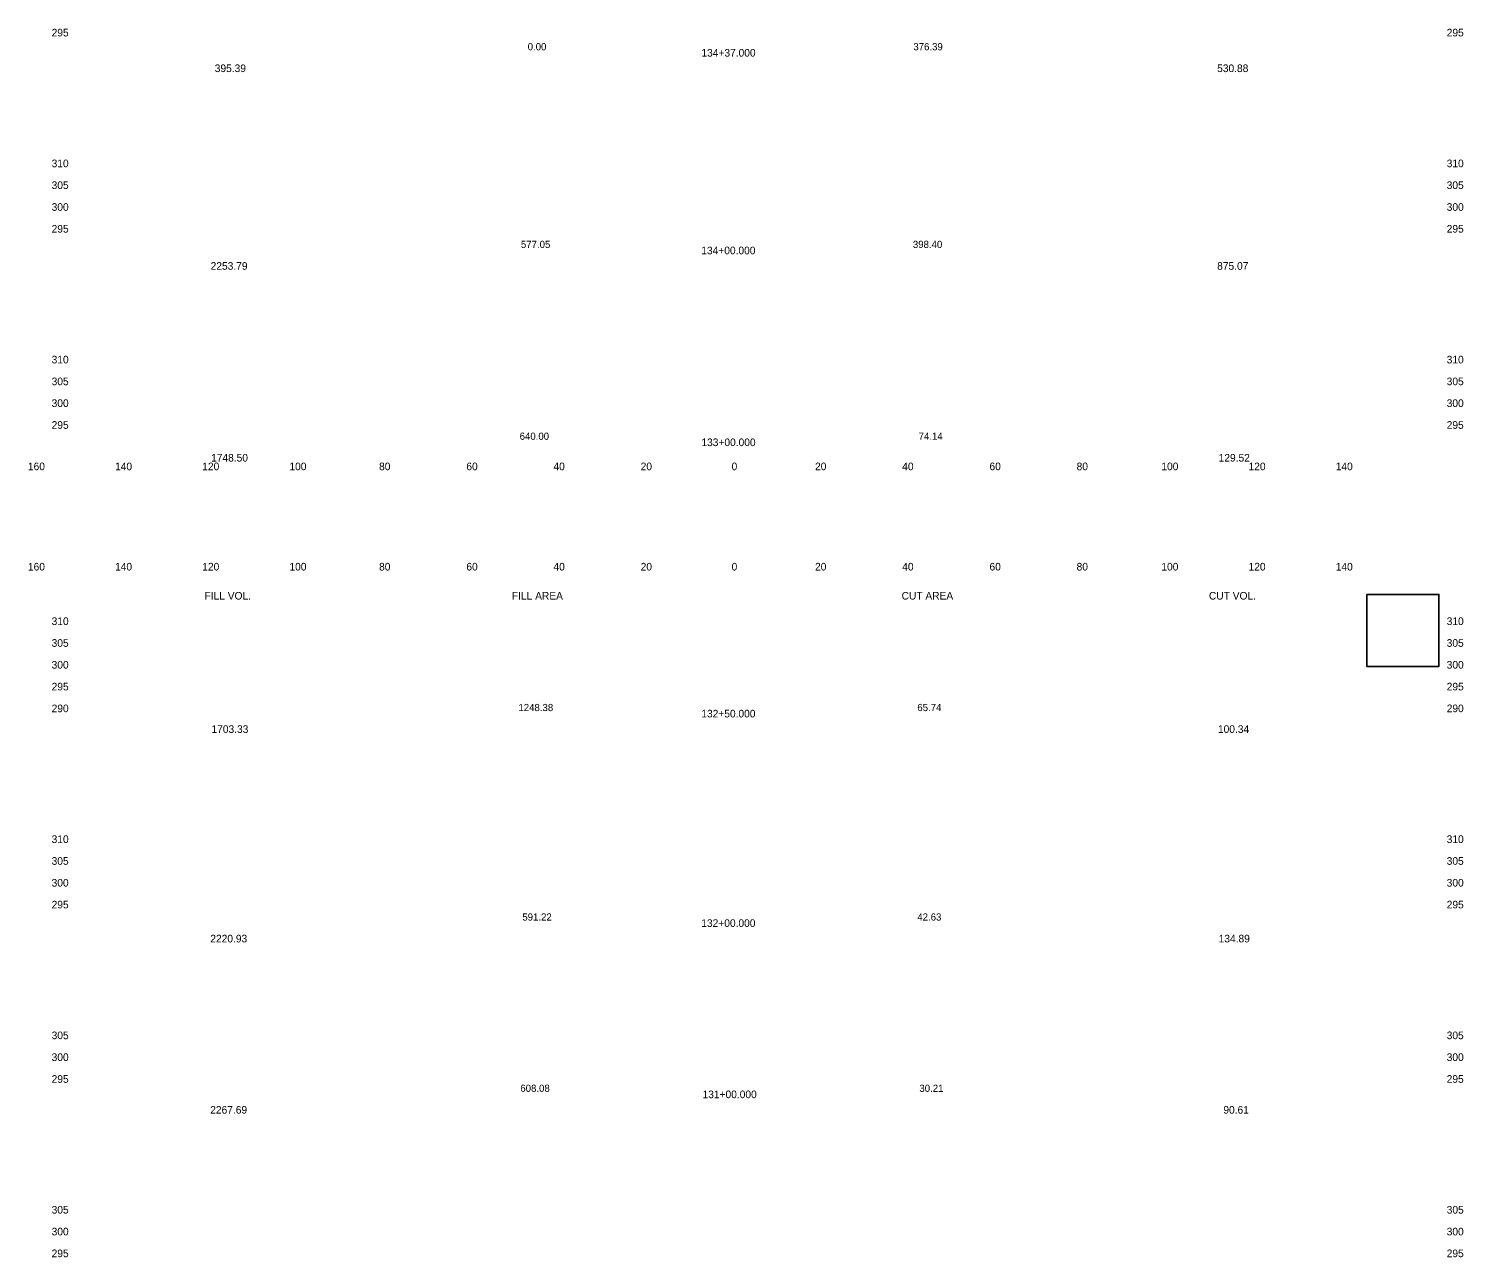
# Model space of a CAD drawing. Extents: x 21477 to 21806, y 6470 to 11049.
# Drawn here: x 21477.1 to 21806.1, y 9049.8 to 9331.6 of the extents above; entities that cross this region are included whole.
import ezdxf

# ---------------------------------------------------------------- set-up
doc = ezdxf.new("R2010")
doc.units = 0
for name, color, linetype in [('SHEET_CONSULTANT_STAMP', 7, 'Continuous'), ('XS_SHEET_EW_TX_AREA', 7, 'Continuous'), ('XS_SHEET_EW_TX_VOLUME', 7, 'Continuous'), ('XS_SHEET_LABELS_ELEVATION', 7, 'Continuous'), ('XS_SHEET_LABELS_OFFSET', 7, 'Continuous'), ('XS_SHEET_LABELS_STATION', 7, 'Continuous'), ('XS_SHEET_TX', 7, 'Continuous')]:
    doc.layers.add(name, color=color, linetype=linetype)

msp = doc.modelspace()

# ---------------------------------------------------------------- linework, layer by layer
at = {"layer": 'SHEET_CONSULTANT_STAMP'}
msp.add_lwpolyline([(21784.04, 9185.34), (21800.54, 9185.34), (21800.54, 9201.84), (21784.04, 9201.84)], close=True, dxfattribs=at)

# ---------------------------------------------------------------- texts
at = {"layer": 'XS_SHEET_EW_TX_AREA'}
for s, p in [(' 0.00 ', (21590.92, 9326.66)), (' 376.39 ', (21679.39, 9326.66)), (' 577.05 ', (21589.37, 9281.32)), (' 398.40 ', (21679.28, 9281.32)), (' 640.00 ', (21589.08, 9237.32)), (' 74.14 ', (21680.6, 9237.32)), (' 1248.38 ', (21588.8, 9175.09)), (' 65.74 ', (21680.3, 9175.09)), (' 591.22 ', (21589.7, 9127.04)), (' 42.63 ', (21680.3, 9127.04)), (' 608.08 ', (21589.24, 9087.76)), (' 30.21 ', (21680.77, 9087.76))]:
    msp.add_text(s, height=1.65, dxfattribs=at).set_placement(p)
at = {"layer": 'XS_SHEET_EW_TX_VOLUME'}
for s, p in [(' 395.39 ', (21519.11, 9321.66)), (' 530.88 ', (21749.04, 9321.66)), (' 2253.79 ', (21518.17, 9276.32)), (' 875.07 ', (21749.04, 9276.32)), (' 1748.50 ', (21518.27, 9232.32)), (' 129.52 ', (21749.38, 9232.32)), (' 1703.33 ', (21518.36, 9170.09)), (' 100.34 ', (21749.22, 9170.09)), (' 2220.93 ', (21518.09, 9122.04)), (' 134.89 ', (21749.38, 9122.04)), (' 2267.69 ', (21518.07, 9082.76)), (' 90.61 ', (21750.46, 9082.76))]:
    msp.add_text(s, height=1.75, dxfattribs=at).set_placement(p)
at = {"layer": 'XS_SHEET_LABELS_ELEVATION'}
for s, p in [('  295  ', (21481.04, 9329.84)), ('  295  ', (21801.04, 9329.84)), ('  310  ', (21481.04, 9299.84)), ('  310  ', (21801.04, 9299.84)), ('  305  ', (21481.04, 9294.84)), ('  305  ', (21801.04, 9294.84)), ('  300  ', (21481.04, 9289.84)), ('  300  ', (21801.04, 9289.84)), ('  295  ', (21481.04, 9284.84)), ('  295  ', (21801.04, 9284.84)), ('  310  ', (21481.04, 9254.84)), ('  310  ', (21801.04, 9254.84)), ('  305  ', (21481.04, 9249.84)), ('  305  ', (21801.04, 9249.84)), ('  300  ', (21481.04, 9244.84)), ('  300  ', (21801.04, 9244.84)), ('  295  ', (21481.04, 9239.84)), ('  295  ', (21801.04, 9239.84)), ('  310  ', (21481.04, 9194.84)), ('  310  ', (21801.04, 9194.84)), ('  305  ', (21481.04, 9189.84)), ('  305  ', (21801.04, 9189.84)), ('  300  ', (21481.04, 9184.84)), ('  300  ', (21801.04, 9184.84)), ('  295  ', (21481.04, 9179.84)), ('  295  ', (21801.04, 9179.84)), ('  290  ', (21481.04, 9174.84)), ('  290  ', (21801.04, 9174.84)), ('  310  ', (21481.04, 9144.84)), ('  310  ', (21801.04, 9144.84)), ('  305  ', (21481.04, 9139.84)), ('  305  ', (21801.04, 9139.84)), ('  300  ', (21481.04, 9134.84)), ('  300  ', (21801.04, 9134.84)), ('  295  ', (21481.04, 9129.84)), ('  295  ', (21801.04, 9129.84)), ('  305  ', (21481.04, 9099.84)), ('  305  ', (21801.04, 9099.84)), ('  300  ', (21481.04, 9094.84)), ('  300  ', (21801.04, 9094.84)), ('  295  ', (21481.04, 9089.84)), ('  295  ', (21801.04, 9089.84)), ('  305  ', (21481.04, 9059.84)), ('  305  ', (21801.04, 9059.84)), ('  300  ', (21481.04, 9054.84)), ('  300  ', (21801.04, 9054.84)), ('  295  ', (21481.04, 9049.84)), ('  295  ', (21801.04, 9049.84))]:
    msp.add_text(s, height=1.75, dxfattribs=at).set_placement(p)
at = {"layer": 'XS_SHEET_LABELS_OFFSET'}
for s, p in [('  160  ', (21475.6, 9230.34)), ('  140  ', (21495.59, 9230.34)), ('  120  ', (21515.59, 9230.34)), ('  100  ', (21535.59, 9230.34)), ('  80  ', (21556.15, 9230.34)), ('  60  ', (21576.17, 9230.34)), ('  40  ', (21596.15, 9230.34)), ('  20  ', (21616.15, 9230.34)), ('  0  ', (21637.01, 9230.34)), ('  0  ', (21637.01, 9230.34)), ('  20  ', (21656.15, 9230.34)), ('  40  ', (21676.15, 9230.34)), ('  60  ', (21696.17, 9230.34)), ('  80  ', (21716.15, 9230.34)), ('  100  ', (21735.59, 9230.34)), ('  120  ', (21755.59, 9230.34)), ('  140  ', (21775.59, 9230.34)), ('  160  ', (21475.6, 9207.34)), ('  140  ', (21495.59, 9207.34)), ('  120  ', (21515.59, 9207.34)), ('  100  ', (21535.59, 9207.34)), ('  80  ', (21556.15, 9207.34)), ('  60  ', (21576.17, 9207.34)), ('  40  ', (21596.15, 9207.34)), ('  20  ', (21616.15, 9207.34)), ('  0  ', (21637.01, 9207.34)), ('  0  ', (21637.01, 9207.34)), ('  20  ', (21656.15, 9207.34)), ('  40  ', (21676.15, 9207.34)), ('  60  ', (21696.17, 9207.34)), ('  80  ', (21716.15, 9207.34)), ('  100  ', (21735.59, 9207.34)), ('  120  ', (21755.59, 9207.34)), ('  140  ', (21775.59, 9207.34))]:
    msp.add_text(s, height=1.75, dxfattribs=at).set_placement(p)
at = {"layer": 'XS_SHEET_LABELS_STATION'}
for s, p in [('  134+37.000  ', (21630.09, 9325.21)), ('  134+00.000  ', (21630.06, 9279.87)), ('  133+00.000  ', (21630.09, 9235.87)), ('  132+50.000  ', (21630.06, 9173.64)), ('  132+00.000  ', (21630.06, 9125.59)), ('  131+00.000  ', (21630.35, 9086.31))]:
    msp.add_text(s, height=1.75, dxfattribs=at).set_placement(p)
at = {"layer": 'XS_SHEET_TX'}
for s, p in [('FILL VOL.', (21517.41, 9200.67)), ('FILL AREA', (21587.92, 9200.67)), ('CUT AREA', (21677.31, 9200.67)), ('CUT VOL.', (21747.8, 9200.67))]:
    msp.add_text(s, height=1.75, dxfattribs=at).set_placement(p)

doc.saveas('drawing.dxf')
